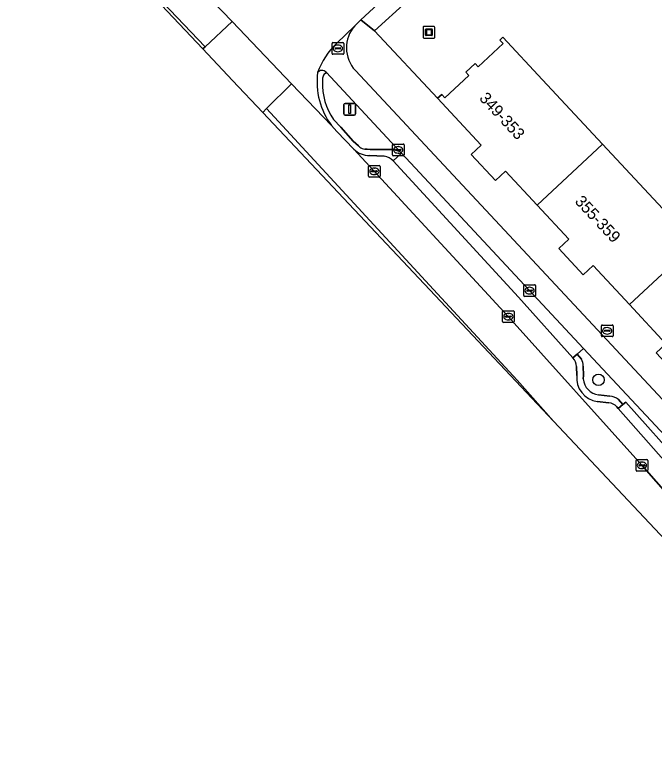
# Model space of a CAD drawing. Extents: x 163147 to 163550, y 380933 to 381639.
# Drawn here: x 163159.2 to 163214.1, y 381137.9 to 381202 of the extents above; entities that cross this region are included whole.
import ezdxf

# ---------------------------------------------------------------- set-up
doc = ezdxf.new("R2010")
doc.units = 0
for name, color, linetype in [('IMGEO_Berm_groen', 7, 'Continuous'), ('IMGEO_Berm_open', 7, 'Continuous'), ('IMGEO_Boom', 7, 'Continuous'), ('IMGEO_Brandkraan', 7, 'Continuous'), ('IMGEO_Erf', 7, 'Continuous'), ('IMGEO_Fietspad_gesloten', 7, 'Continuous'), ('IMGEO_Kolk', 7, 'Continuous'), ('IMGEO_Kunstobject', 7, 'Continuous'), ('IMGEO_Lichtmast', 7, 'Continuous'), ('IMGEO_Pand', 7, 'Continuous'), ('IMGEO_Pand_nummerreeks', 7, 'Continuous'), ('IMGEO_Parkeervlak_open', 7, 'Continuous'), ('IMGEO_Rijbaan_lokaal_gesloten', 7, 'Continuous'), ('IMGEO_Rijbaan_lokaal_open', 7, 'Continuous'), ('IMGEO_Voetpad_open', 7, 'Continuous')]:
    doc.layers.add(name, color=color, linetype=linetype)

msp = doc.modelspace()

# ---------------------------------------------------------------- linework, layer by layer
at = {"layer": 'IMGEO_Berm_groen'}
for points in [[(163185.926, 381197.07), (163185.82, 381196.99)], [(163191.896, 381190.415), (163192.218, 381190.305), (163185.926, 381197.07)], [(163186.546, 381193.048), (163187.152, 381192.375), (163188.228, 381191.18), (163188.67, 381190.782), (163188.792, 381190.677)], [(163189.216, 381190.502), (163189.433, 381190.489), (163189.689, 381190.475), (163191.322, 381190.475), (163191.552, 381190.471)], [(163208.015, 381173.372), (163207.465, 381172.885), (163207.843, 381172.459)], [(163211.002, 381168.987), (163211.372, 381168.554), (163211.631, 381168.775), (163216.584, 381163.212), (163217.075, 381163.662), (163208.015, 381173.372)], [(163207.971, 381171.861), (163207.988, 381171.064), (163207.985, 381170.754)], [(163209.285, 381169.389), (163210.25, 381169.273)]]:
    msp.add_lwpolyline(points, dxfattribs=at)
for centre, radius, start, end in [((163188.035, 381196.302), 2.449, 171.02195, 179.97367), ((163186.1, 381196.583), 0.494, 124.46865, 168.15122), ((163190.94, 381196.113), 5.357, 177.9675, 214.89733), ((163189.269, 381191.232), 0.732, 229.31132, 265.8333), ((163191.491, 381189.012), 1.46, 73.90078, 87.60699), ((163206.548, 381171.869), 1.423, 359.67681, 24.48653), ((163209.469, 381170.865), 1.488, 184.29341, 262.91223), ((163210.118, 381167.794), 1.485, 53.4572, 84.89726)]:
    msp.add_arc(centre, radius, start, end, dxfattribs=at)
at = {"layer": 'IMGEO_Berm_open'}
for points in [[(163185.82, 381196.99), (163185.926, 381197.07), (163185.896, 381197.102)], [(163188.792, 381190.677), (163188.67, 381190.782), (163188.228, 381191.18), (163187.152, 381192.375), (163186.546, 381193.048)], [(163186.374, 381192.526), (163186.819, 381192.001), (163188.282, 381190.507)], [(163191.552, 381190.471), (163191.322, 381190.475), (163189.689, 381190.475), (163189.433, 381190.489), (163189.216, 381190.502)], [(163191.647, 381189.49), (163192.37, 381190.141), (163192.218, 381190.305), (163191.896, 381190.415)], [(163189.635, 381189.963), (163190.893, 381189.904)], [(163207.843, 381172.459), (163207.465, 381172.885), (163207.099, 381172.561)], [(163207.401, 381171.835), (163207.418, 381171.061)], [(163207.985, 381170.754), (163207.988, 381171.064), (163207.971, 381171.861)], [(163209.188, 381168.826), (163210.171, 381168.708)], [(163210.25, 381169.273), (163209.285, 381169.389)], [(163210.852, 381168.362), (163210.979, 381168.218), (163211.372, 381168.554), (163211.002, 381168.987)]]:
    msp.add_lwpolyline(points, dxfattribs=at)
for centre, radius, start, end in [((163191.31, 381196.258), 6.188, 172.42176, 217.09265), ((163185.548, 381196.783), 0.472, 42.45989, 141.99421), ((163188.035, 381196.302), 2.449, 171.02195, 179.97367), ((163186.1, 381196.583), 0.494, 124.46865, 168.15122), ((163190.94, 381196.113), 5.357, 177.9675, 214.89733), ((163189.269, 381191.232), 0.732, 229.31132, 265.8333), ((163189.547, 381191.698), 1.737, 223.27697, 272.91592), ((163191.491, 381189.012), 1.46, 73.90078, 87.60699), ((163190.677, 381188.618), 1.304, 41.97808, 80.48204), ((163206.408, 381171.848), 0.993, 359.2601, 45.91236), ((163206.548, 381171.869), 1.423, 359.67681, 24.48653), ((163209.465, 381170.864), 2.057, 174.50423, 262.25044), ((163209.469, 381170.865), 1.488, 184.29341, 262.91223), ((163210.118, 381167.794), 1.485, 53.4572, 84.89726), ((163210.09, 381167.706), 1.005, 40.74221, 85.3897)]:
    msp.add_arc(centre, radius, start, end, dxfattribs=at)
at = {"layer": 'IMGEO_Boom'}
msp.add_circle((163209.29, 381170.678), 0.489, dxfattribs=at)
at = {"layer": 'IMGEO_Brandkraan'}
for p, q in [((163186.484, 381199.647), (163187.336, 381199.647)), ((163186.409, 381198.721), (163186.409, 381199.573)), ((163186.668, 381199.141), (163186.668, 381199.153)), ((163187.106, 381199.104), (163186.708, 381199.104)), ((163186.711, 381199.19), (163187.109, 381199.19)), ((163186.897, 381199.427), (163186.922, 381199.427)), ((163187.152, 381199.153), (163187.152, 381199.141)), ((163187.41, 381199.573), (163187.41, 381198.721)), ((163187.336, 381198.647), (163186.484, 381198.647)), ((163186.92, 381198.867), (163186.895, 381198.867)), ((163209.534, 381174.465), (163209.534, 381175.317)), ((163209.609, 381175.391), (163210.461, 381175.391)), ((163210.535, 381175.317), (163210.535, 381174.465)), ((163209.793, 381174.885), (163209.793, 381174.897)), ((163210.231, 381174.848), (163209.833, 381174.848)), ((163209.836, 381174.934), (163210.234, 381174.934)), ((163210.045, 381174.611), (163210.02, 381174.611)), ((163210.022, 381175.171), (163210.047, 381175.171)), ((163210.277, 381174.897), (163210.277, 381174.885)), ((163210.461, 381174.391), (163209.609, 381174.391))]:
    msp.add_line(p, q, dxfattribs=at)
for points in [[(163186.484, 381199.647), (163187.336, 381199.647)], [(163186.409, 381198.721), (163186.409, 381199.573)], [(163187.41, 381199.573), (163187.41, 381198.721)], [(163187.336, 381198.647), (163186.484, 381198.647)], [(163209.534, 381174.465), (163209.534, 381175.317)], [(163209.609, 381175.391), (163210.461, 381175.391)], [(163210.535, 381175.317), (163210.535, 381174.465)], [(163210.461, 381174.391), (163209.609, 381174.391)]]:
    msp.add_lwpolyline(points, dxfattribs=at)
for centre, radius, start, end in [((163186.486, 381199.571), 0.0765, 91.55205, 178.44795), ((163186.486, 381199.571), 0.0765, 91.55205, 178.44795), ((163187.334, 381199.571), 0.0765, 1.55205, 88.44795), ((163187.334, 381199.571), 0.0765, 1.55205, 88.44795), ((163186.708, 381199.15), 0.0403, 85.87752, 175.75265), ((163186.705, 381199.14), 0.0366, 178.93798, 274.71019), ((163187.109, 381199.147), 0.043, 264.86636, 352.45326), ((163187.113, 381199.152), 0.0386, 1.73085, 96.63898), ((163186.486, 381198.723), 0.0765, 181.55205, 268.44795), ((163186.486, 381198.723), 0.0765, 181.55205, 268.44795), ((163187.334, 381198.723), 0.0765, 271.55205, 358.44795), ((163187.334, 381198.723), 0.0765, 271.55205, 358.44795), ((163209.611, 381175.315), 0.0765, 91.55205, 178.44795), ((163209.611, 381175.315), 0.0765, 91.55205, 178.44795), ((163210.459, 381175.315), 0.0765, 1.55205, 88.44795), ((163210.459, 381175.315), 0.0765, 1.55205, 88.44795), ((163209.833, 381174.894), 0.0403, 85.87752, 175.75265), ((163209.83, 381174.884), 0.0366, 178.93798, 274.71019), ((163210.234, 381174.891), 0.043, 264.86636, 352.45326), ((163210.238, 381174.896), 0.0386, 1.73085, 96.63898), ((163209.611, 381174.467), 0.0765, 181.55205, 268.44795), ((163209.611, 381174.467), 0.0765, 181.55205, 268.44795), ((163210.459, 381174.467), 0.0765, 271.55205, 358.44795), ((163210.459, 381174.467), 0.0765, 271.55205, 358.44795)]:
    msp.add_arc(centre, radius, start, end, dxfattribs=at)
for centre, major_axis, ratio, start_param, end_param in [((163186.896, 381199.147), (-0.387, 0.002), 0.722429, 4.712389, 7.853982), ((163186.921, 381199.147), (-0.39, 0.002), 0.717154, 1.570796, 4.712389), ((163210.021, 381174.891), (-0.387, 0.002), 0.722429, 4.712389, 7.853982), ((163210.046, 381174.891), (-0.39, 0.002), 0.717154, 1.570796, 4.712389)]:
    msp.add_ellipse(centre, major_axis=major_axis, ratio=ratio, start_param=start_param, end_param=end_param, dxfattribs=at)
at = {"layer": 'IMGEO_Erf'}
msp.add_lwpolyline([(163214.572, 381217.942), (163212.265, 381220.831), (163190.07, 381200.655), (163195.477, 381194.868), (163195.836, 381195.203), (163196.101, 381194.918), (163198.153, 381196.828), (163197.893, 381197.108), (163198.687, 381197.847), (163198.948, 381197.567), (163201.093, 381199.563), (163200.818, 381199.859), (163201.087, 381200.11), (163204.494, 381196.451), (163209.644, 381190.918), (163217.586, 381182.386)], dxfattribs=at)
at = {"layer": 'IMGEO_Fietspad_gesloten'}
for points in [[(163188.367, 381201.099), (163186.803, 381199.584)], [(163185.896, 381197.102), (163185.926, 381197.07), (163192.218, 381190.305), (163192.37, 381190.141), (163208.015, 381173.372), (163217.075, 381163.662), (163217.693, 381163), (163225.596, 381154.531), (163226.222, 381153.861), (163232.791, 381146.822), (163236.873, 381142.447), (163243.701, 381135.131)], [(163431.634, 380936.983), (163426.381, 380942.59), (163389.734, 380981.756), (163386.168, 380985.564), (163372.648, 381000), (163319.829, 381056.397), (163310.14, 381066.773), (163306.558, 381070.608), (163278.278, 381100.892), (163188.415, 381197.241)]]:
    msp.add_lwpolyline(points, dxfattribs=at)
for centre, radius, start, end in [((163190.531, 381199.197), 2.882, 138.68571, 222.73992), ((163191.181, 381194.964), 6.365, 133.45806, 160.63875), ((163185.548, 381196.783), 0.472, 42.45989, 141.99421)]:
    msp.add_arc(centre, radius, start, end, dxfattribs=at)
at = {"layer": 'IMGEO_Kolk'}
for p, q in [((163191.593, 381190.009), (163191.593, 381190.861)), ((163191.668, 381190.935), (163192.52, 381190.935)), ((163192.081, 381190.715), (163192.106, 381190.715)), ((163192.594, 381190.861), (163192.594, 381190.009)), ((163191.852, 381190.429), (163191.852, 381190.441)), ((163192.29, 381190.392), (163191.892, 381190.392)), ((163191.895, 381190.478), (163192.293, 381190.478)), ((163192.104, 381190.155), (163192.079, 381190.155)), ((163192.336, 381190.441), (163192.336, 381190.429)), ((163192.52, 381189.935), (163191.668, 381189.935)), ((163189.543, 381188.165), (163189.543, 381189.017)), ((163189.618, 381189.091), (163190.47, 381189.091)), ((163190.031, 381188.871), (163190.056, 381188.871)), ((163190.544, 381189.017), (163190.544, 381188.165)), ((163190.47, 381188.091), (163189.618, 381188.091)), ((163189.802, 381188.585), (163189.802, 381188.597)), ((163190.24, 381188.548), (163189.842, 381188.548)), ((163189.845, 381188.634), (163190.243, 381188.634)), ((163190.054, 381188.311), (163190.029, 381188.311)), ((163190.286, 381188.597), (163190.286, 381188.585)), ((163202.866, 381177.925), (163202.866, 381178.777)), ((163202.941, 381178.851), (163203.793, 381178.851)), ((163203.354, 381178.631), (163203.379, 381178.631)), ((163203.867, 381178.777), (163203.867, 381177.925)), ((163203.793, 381177.851), (163202.941, 381177.851)), ((163203.125, 381178.345), (163203.125, 381178.357)), ((163203.563, 381178.308), (163203.165, 381178.308)), ((163203.168, 381178.394), (163203.566, 381178.394)), ((163203.377, 381178.071), (163203.352, 381178.071)), ((163203.609, 381178.357), (163203.609, 381178.345)), ((163201.049, 381175.686), (163201.049, 381176.538)), ((163201.124, 381176.612), (163201.976, 381176.612)), ((163202.05, 381176.538), (163202.05, 381175.686)), ((163201.308, 381176.106), (163201.308, 381176.118)), ((163201.746, 381176.069), (163201.348, 381176.069)), ((163201.351, 381176.155), (163201.749, 381176.155)), ((163201.537, 381176.392), (163201.562, 381176.392)), ((163201.792, 381176.118), (163201.792, 381176.106)), ((163201.976, 381175.612), (163201.124, 381175.612)), ((163201.56, 381175.832), (163201.535, 381175.832)), ((163212.514, 381162.908), (163212.514, 381163.76)), ((163212.589, 381163.834), (163213.441, 381163.834)), ((163213.515, 381163.76), (163213.515, 381162.908)), ((163212.773, 381163.328), (163212.773, 381163.34)), ((163213.211, 381163.291), (163212.813, 381163.291)), ((163212.816, 381163.377), (163213.214, 381163.377)), ((163213.002, 381163.614), (163213.027, 381163.614)), ((163213.257, 381163.34), (163213.257, 381163.328)), ((163213.441, 381162.834), (163212.589, 381162.834)), ((163213.025, 381163.054), (163213, 381163.054))]:
    msp.add_line(p, q, dxfattribs=at)
for points in [[(163191.593, 381190.009), (163191.593, 381190.861)], [(163191.668, 381190.935), (163192.52, 381190.935)], [(163192.594, 381190.861), (163192.594, 381190.009)], [(163192.52, 381189.935), (163191.668, 381189.935)], [(163189.543, 381188.165), (163189.543, 381189.017)], [(163189.618, 381189.091), (163190.47, 381189.091)], [(163190.544, 381189.017), (163190.544, 381188.165)], [(163190.47, 381188.091), (163189.618, 381188.091)], [(163202.866, 381177.925), (163202.866, 381178.777)], [(163202.941, 381178.851), (163203.793, 381178.851)], [(163203.867, 381178.777), (163203.867, 381177.925)], [(163203.793, 381177.851), (163202.941, 381177.851)], [(163201.049, 381175.686), (163201.049, 381176.538)], [(163201.124, 381176.612), (163201.976, 381176.612)], [(163202.05, 381176.538), (163202.05, 381175.686)], [(163201.976, 381175.612), (163201.124, 381175.612)], [(163212.514, 381162.908), (163212.514, 381163.76)], [(163212.589, 381163.834), (163213.441, 381163.834)], [(163213.515, 381163.76), (163213.515, 381162.908)], [(163213.441, 381162.834), (163212.589, 381162.834)]]:
    msp.add_lwpolyline(points, dxfattribs=at)
for centre, radius, start, end in [((163191.67, 381190.859), 0.0765, 91.55205, 178.44795), ((163191.67, 381190.859), 0.0765, 91.55205, 178.44795), ((163192.518, 381190.859), 0.0765, 1.55205, 88.44795), ((163192.518, 381190.859), 0.0765, 1.55205, 88.44795), ((163191.67, 381190.011), 0.0765, 181.55205, 268.44795), ((163191.67, 381190.011), 0.0765, 181.55205, 268.44795), ((163191.892, 381190.438), 0.0403, 85.87752, 175.75265), ((163191.889, 381190.428), 0.0366, 178.93798, 274.71019), ((163192.293, 381190.435), 0.043, 264.86636, 352.45326), ((163192.297, 381190.44), 0.0386, 1.73085, 96.63898), ((163192.518, 381190.011), 0.0765, 271.55205, 358.44795), ((163192.518, 381190.011), 0.0765, 271.55205, 358.44795), ((163189.62, 381189.015), 0.0765, 91.55205, 178.44795), ((163189.62, 381189.015), 0.0765, 91.55205, 178.44795), ((163190.468, 381189.015), 0.0765, 1.55205, 88.44795), ((163190.468, 381189.015), 0.0765, 1.55205, 88.44795), ((163189.62, 381188.167), 0.0765, 181.55205, 268.44795), ((163189.62, 381188.167), 0.0765, 181.55205, 268.44795), ((163189.842, 381188.594), 0.0403, 85.87752, 175.75265), ((163189.839, 381188.584), 0.0366, 178.93798, 274.71019), ((163190.243, 381188.591), 0.043, 264.86636, 352.45326), ((163190.247, 381188.596), 0.0386, 1.73085, 96.63898), ((163190.468, 381188.167), 0.0765, 271.55205, 358.44795), ((163190.468, 381188.167), 0.0765, 271.55205, 358.44795), ((163202.943, 381178.775), 0.0765, 91.55205, 178.44795), ((163202.943, 381178.775), 0.0765, 91.55205, 178.44795), ((163203.791, 381178.775), 0.0765, 1.55205, 88.44795), ((163203.791, 381178.775), 0.0765, 1.55205, 88.44795), ((163202.943, 381177.927), 0.0765, 181.55205, 268.44795), ((163202.943, 381177.927), 0.0765, 181.55205, 268.44795), ((163203.165, 381178.354), 0.0403, 85.87752, 175.75265), ((163203.162, 381178.344), 0.0366, 178.93798, 274.71019), ((163203.566, 381178.351), 0.043, 264.86636, 352.45326), ((163203.57, 381178.356), 0.0386, 1.73085, 96.63898), ((163203.791, 381177.927), 0.0765, 271.55205, 358.44795), ((163203.791, 381177.927), 0.0765, 271.55205, 358.44795), ((163201.126, 381176.536), 0.0765, 91.55205, 178.44795), ((163201.126, 381176.536), 0.0765, 91.55205, 178.44795), ((163201.974, 381176.536), 0.0765, 1.55205, 88.44795), ((163201.974, 381176.536), 0.0765, 1.55205, 88.44795), ((163201.348, 381176.115), 0.0403, 85.87752, 175.75265), ((163201.345, 381176.105), 0.0366, 178.93798, 274.71019), ((163201.749, 381176.112), 0.043, 264.86636, 352.45326), ((163201.753, 381176.117), 0.0386, 1.73085, 96.63898), ((163201.126, 381175.688), 0.0765, 181.55205, 268.44795), ((163201.126, 381175.688), 0.0765, 181.55205, 268.44795), ((163201.974, 381175.688), 0.0765, 271.55205, 358.44795), ((163201.974, 381175.688), 0.0765, 271.55205, 358.44795), ((163212.591, 381163.758), 0.0765, 91.55205, 178.44795), ((163212.591, 381163.758), 0.0765, 91.55205, 178.44795), ((163213.439, 381163.758), 0.0765, 1.55205, 88.44795), ((163213.439, 381163.758), 0.0765, 1.55205, 88.44795), ((163212.813, 381163.337), 0.0403, 85.87752, 175.75265), ((163212.81, 381163.327), 0.0366, 178.93798, 274.71019), ((163213.214, 381163.334), 0.043, 264.86636, 352.45326), ((163213.218, 381163.339), 0.0386, 1.73085, 96.63898), ((163212.591, 381162.91), 0.0765, 181.55205, 268.44795), ((163212.591, 381162.91), 0.0765, 181.55205, 268.44795), ((163213.439, 381162.91), 0.0765, 271.55205, 358.44795), ((163213.439, 381162.91), 0.0765, 271.55205, 358.44795)]:
    msp.add_arc(centre, radius, start, end, dxfattribs=at)
for centre, major_axis, ratio, start_param, end_param in [((163192.08, 381190.435), (-0.387, 0.002), 0.722429, 4.712389, 7.853982), ((163192.105, 381190.435), (-0.39, 0.002), 0.717154, 1.570796, 4.712389), ((163190.03, 381188.591), (-0.387, 0.002), 0.722429, 4.712389, 7.853982), ((163190.055, 381188.591), (-0.39, 0.002), 0.717154, 1.570796, 4.712389), ((163203.353, 381178.351), (-0.387, 0.002), 0.722429, 4.712389, 7.853982), ((163203.378, 381178.351), (-0.39, 0.002), 0.717154, 1.570796, 4.712389), ((163201.536, 381176.112), (-0.387, 0.002), 0.722429, 4.712389, 7.853982), ((163201.561, 381176.112), (-0.39, 0.002), 0.717154, 1.570796, 4.712389), ((163213.001, 381163.334), (-0.387, 0.002), 0.722429, 4.712389, 7.853982), ((163213.026, 381163.334), (-0.39, 0.002), 0.717154, 1.570796, 4.712389)]:
    msp.add_ellipse(centre, major_axis=major_axis, ratio=ratio, start_param=start_param, end_param=end_param, dxfattribs=at)
at = {"layer": 'IMGEO_Kunstobject'}
for p, q in [((163194.229, 381200.949), (163194.229, 381200.108)), ((163194.229, 381200.949), (163194.229, 381200.108)), ((163195.145, 381201.033), (163194.304, 381201.033)), ((163195.145, 381201.033), (163194.304, 381201.033)), ((163195.229, 381200.117), (163195.229, 381200.958)), ((163195.229, 381200.117), (163195.229, 381200.958)), ((163194.443, 381200.297), (163194.443, 381200.771)), ((163194.493, 381200.821), (163194.967, 381200.821)), ((163194.967, 381200.247), (163194.493, 381200.247)), ((163194.523, 381200.721), (163194.523, 381200.347)), ((163194.917, 381200.741), (163194.543, 381200.741)), ((163194.543, 381200.327), (163194.917, 381200.327)), ((163194.937, 381200.347), (163194.937, 381200.721)), ((163195.017, 381200.771), (163195.017, 381200.297)), ((163194.313, 381200.033), (163195.154, 381200.033)), ((163194.313, 381200.033), (163195.154, 381200.033))]:
    msp.add_line(p, q, dxfattribs=at)
for centre, radius, start, end in [((163194.307, 381200.955), 0.0779, 92.4484, 184.28452), ((163194.307, 381200.955), 0.0779, 92.4484, 184.28452), ((163195.151, 381200.955), 0.0779, 2.4484, 94.28452), ((163195.151, 381200.955), 0.0779, 2.4484, 94.28452), ((163194.493, 381200.771), 0.05, 90, 180), ((163194.493, 381200.297), 0.05, 180, 270), ((163194.543, 381200.721), 0.02, 90, 180), ((163194.543, 381200.347), 0.02, 180, 270), ((163194.917, 381200.721), 0.02, 360, 90), ((163194.917, 381200.347), 0.02, 270, 0), ((163194.967, 381200.771), 0.05, 360, 90), ((163194.967, 381200.297), 0.05, 270, 0), ((163194.307, 381200.111), 0.0779, 182.4484, 274.28452), ((163194.307, 381200.111), 0.0779, 182.4484, 274.28452), ((163195.151, 381200.111), 0.0779, 272.4484, 4.28452), ((163195.151, 381200.111), 0.0779, 272.4484, 4.28452)]:
    msp.add_arc(centre, radius, start, end, dxfattribs=at)
at = {"layer": 'IMGEO_Lichtmast'}
for p, q in [((163187.435, 381193.524), (163187.435, 381194.324)), ((163187.435, 381194.324), (163187.435, 381193.524)), ((163187.535, 381194.424), (163188.325, 381194.424)), ((163188.325, 381194.424), (163187.535, 381194.424)), ((163188.425, 381194.324), (163188.425, 381193.524)), ((163188.425, 381193.524), (163188.425, 381194.324)), ((163188.325, 381193.424), (163187.535, 381193.424)), ((163187.535, 381193.424), (163188.325, 381193.424))]:
    msp.add_line(p, q, dxfattribs=at)
msp.add_lwpolyline([(163187.855, 381194.299), (163188.005, 381194.299), (163188.005, 381193.549), (163187.855, 381193.549), (163187.855, 381194.299)], dxfattribs=at)
for centre, start, end in [((163187.535, 381194.324), 90, 180), ((163187.535, 381194.324), 90, 180), ((163188.325, 381194.324), 0, 90), ((163188.325, 381194.324), 360, 90), ((163187.535, 381193.524), 180, 270), ((163187.535, 381193.524), 180, 270), ((163188.325, 381193.524), 270, 0), ((163188.325, 381193.524), 270, 0)]:
    msp.add_arc(centre, 0.1, start, end, dxfattribs=at)
at = {"layer": 'IMGEO_Pand'}
for points in [[(163209.644, 381190.918), (163204.494, 381196.451), (163201.087, 381200.11), (163200.818, 381199.859), (163201.093, 381199.563), (163198.948, 381197.567), (163198.687, 381197.847), (163197.893, 381197.108), (163198.153, 381196.828), (163196.101, 381194.918), (163195.836, 381195.203), (163195.477, 381194.868), (163199.226, 381190.839), (163198.365, 381190.038), (163200.446, 381187.803), (163201.311, 381188.609), (163204.028, 381185.69)], [(163217.586, 381182.386), (163209.644, 381190.918), (163204.028, 381185.69), (163206.745, 381182.771), (163205.876, 381181.962), (163207.975, 381179.707), (163208.829, 381180.501), (163211.955, 381177.143)], [(163217.586, 381182.386), (163211.955, 381177.143), (163215.08, 381173.786), (163214.239, 381173.003), (163216.319, 381170.768), (163217.177, 381171.567), (163219.923, 381168.617), (163225.538, 381173.845)]]:
    msp.add_lwpolyline(points, close=True, dxfattribs=at)
at = {"layer": 'IMGEO_Parkeervlak_open'}
for points in [[(163188.282, 381190.507), (163201.535, 381176.127), (163213.012, 381163.337), (163224.088, 381150.736)], [(163190.893, 381189.904), (163189.635, 381189.963)], [(163207.099, 381172.561), (163202.428, 381177.783), (163191.647, 381189.49)], [(163207.418, 381171.061), (163207.401, 381171.835)], [(163210.171, 381168.708), (163209.188, 381168.826)], [(163210.979, 381168.218), (163210.852, 381168.362)], [(163227.456, 381149.558), (163210.979, 381168.218)]]:
    msp.add_lwpolyline(points, dxfattribs=at)
for centre, radius, start, end in [((163189.547, 381191.698), 1.737, 223.27697, 272.91592), ((163190.677, 381188.618), 1.304, 41.97808, 80.48204), ((163206.408, 381171.848), 0.993, 359.2601, 45.91236), ((163209.465, 381170.864), 2.057, 174.50423, 262.25044), ((163210.09, 381167.706), 1.005, 40.74221, 85.3897)]:
    msp.add_arc(centre, radius, start, end, dxfattribs=at)
at = {"layer": 'IMGEO_Rijbaan_lokaal_gesloten'}
for points in [[(163163.793, 381216.185), (163159.956, 381220.195), (163159.79, 381220.368), (163159.209, 381216.417), (163175.52, 381199.28), (163177.822, 381201.461), (163174.435, 381205), (163174.236, 381205.208)], [(163159.184, 381216.249), (163169.229, 381205.581), (163175.331, 381199.101), (163175.52, 381199.28), (163159.209, 381216.417)], [(163180.456, 381193.658), (163180.782, 381193.98), (163182.94, 381196.113), (163177.822, 381201.461), (163175.52, 381199.28), (163175.331, 381199.101), (163177.874, 381196.4)], [(163205.425, 381167.139), (163202.317, 381170.657), (163180.782, 381193.98), (163180.456, 381193.658)]]:
    msp.add_lwpolyline(points, close=True, dxfattribs=at)
msp.add_lwpolyline([(163224.088, 381150.736), (163213.012, 381163.337), (163201.535, 381176.127), (163188.282, 381190.507), (163186.819, 381192.001), (163186.374, 381192.526), (163182.94, 381196.113), (163180.782, 381193.98), (163202.317, 381170.657), (163205.425, 381167.139), (163224.239, 381147.157)], dxfattribs=at)
at = {"layer": 'IMGEO_Rijbaan_lokaal_open'}
for points in [[(163186.803, 381199.584), (163188.367, 381201.099), (163188.702, 381201.423), (163188.892, 381201.601), (163190.329, 381202.954), (163213.677, 381224.249)], [(163174.435, 381205), (163177.822, 381201.461), (163182.94, 381196.113), (163186.374, 381192.526)]]:
    msp.add_lwpolyline(points, dxfattribs=at)
for centre, radius, start, end in [((163191.181, 381194.964), 6.365, 133.45806, 160.63875), ((163191.31, 381196.258), 6.188, 172.42176, 217.09265)]:
    msp.add_arc(centre, radius, start, end, dxfattribs=at)
at = {"layer": 'IMGEO_Voetpad_open'}
for points in [[(163238.786, 381247.234), (163235.706, 381244.458), (163223.919, 381233.668), (163221.799, 381231.758), (163219.855, 381229.989), (163213.677, 381224.249), (163190.329, 381202.954), (163188.892, 381201.601), (163190.07, 381200.655), (163212.265, 381220.831), (163214.572, 381217.942), (163217.096, 381219.943), (163214.736, 381223.024), (163215.881, 381224.069), (163240.64, 381246.663)], [(163215.08, 381173.786), (163211.955, 381177.143), (163208.829, 381180.501), (163207.975, 381179.707), (163205.876, 381181.962), (163206.745, 381182.771), (163204.028, 381185.69), (163201.311, 381188.609), (163200.446, 381187.803), (163198.365, 381190.038), (163199.226, 381190.839), (163195.477, 381194.868), (163190.07, 381200.655), (163188.892, 381201.601), (163188.702, 381201.423), (163188.367, 381201.099)], [(163188.415, 381197.241), (163278.278, 381100.892), (163306.558, 381070.608)]]:
    msp.add_lwpolyline(points, dxfattribs=at)
for points in [[(163192.37, 381190.141), (163191.647, 381189.49), (163202.428, 381177.783), (163207.099, 381172.561), (163207.465, 381172.885), (163208.015, 381173.372)], [(163211.631, 381168.775), (163211.372, 381168.554), (163210.979, 381168.218), (163227.456, 381149.558), (163227.816, 381149.975), (163228.001, 381150.189), (163225.441, 381153.121), (163226.222, 381153.861), (163225.596, 381154.531), (163224.835, 381153.828), (163221.196, 381157.962), (163217.189, 381162.537), (163217.693, 381163), (163217.075, 381163.662), (163216.584, 381163.212)]]:
    msp.add_lwpolyline(points, close=True, dxfattribs=at)
msp.add_arc((163190.531, 381199.197), 2.882, 138.68571, 222.73992, dxfattribs=at)

# ---------------------------------------------------------------- texts
at = {"layer": 'IMGEO_Pand_nummerreeks'}
for s, rotation, p in [('349-353', 312.74729, (163198.991, 381194.82)), ('355-359', 312.99045, (163207.194, 381185.958))]:
    msp.add_text(s, height=1, rotation=rotation, dxfattribs=at).set_placement(p)

doc.saveas('drawing.dxf')
